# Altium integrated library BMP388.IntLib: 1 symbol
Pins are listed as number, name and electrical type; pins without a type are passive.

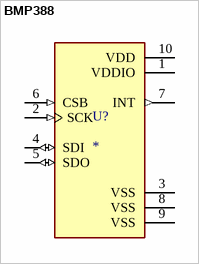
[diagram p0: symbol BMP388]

## BMP388
designator U?
P-Sensor SPI I2C 1, 25 Bar SMD; MP: BMP388
footprint PQFN50P200X200X80-10N
pins: 1 VDDIO (power), 2 SCK (in), 3 VSS (power), 4 SDI (io), 5 SDO (io), 6 CSB (in), 7 INT (out), 8 VSS (power), 9 VSS (power), 10 VDD (power)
